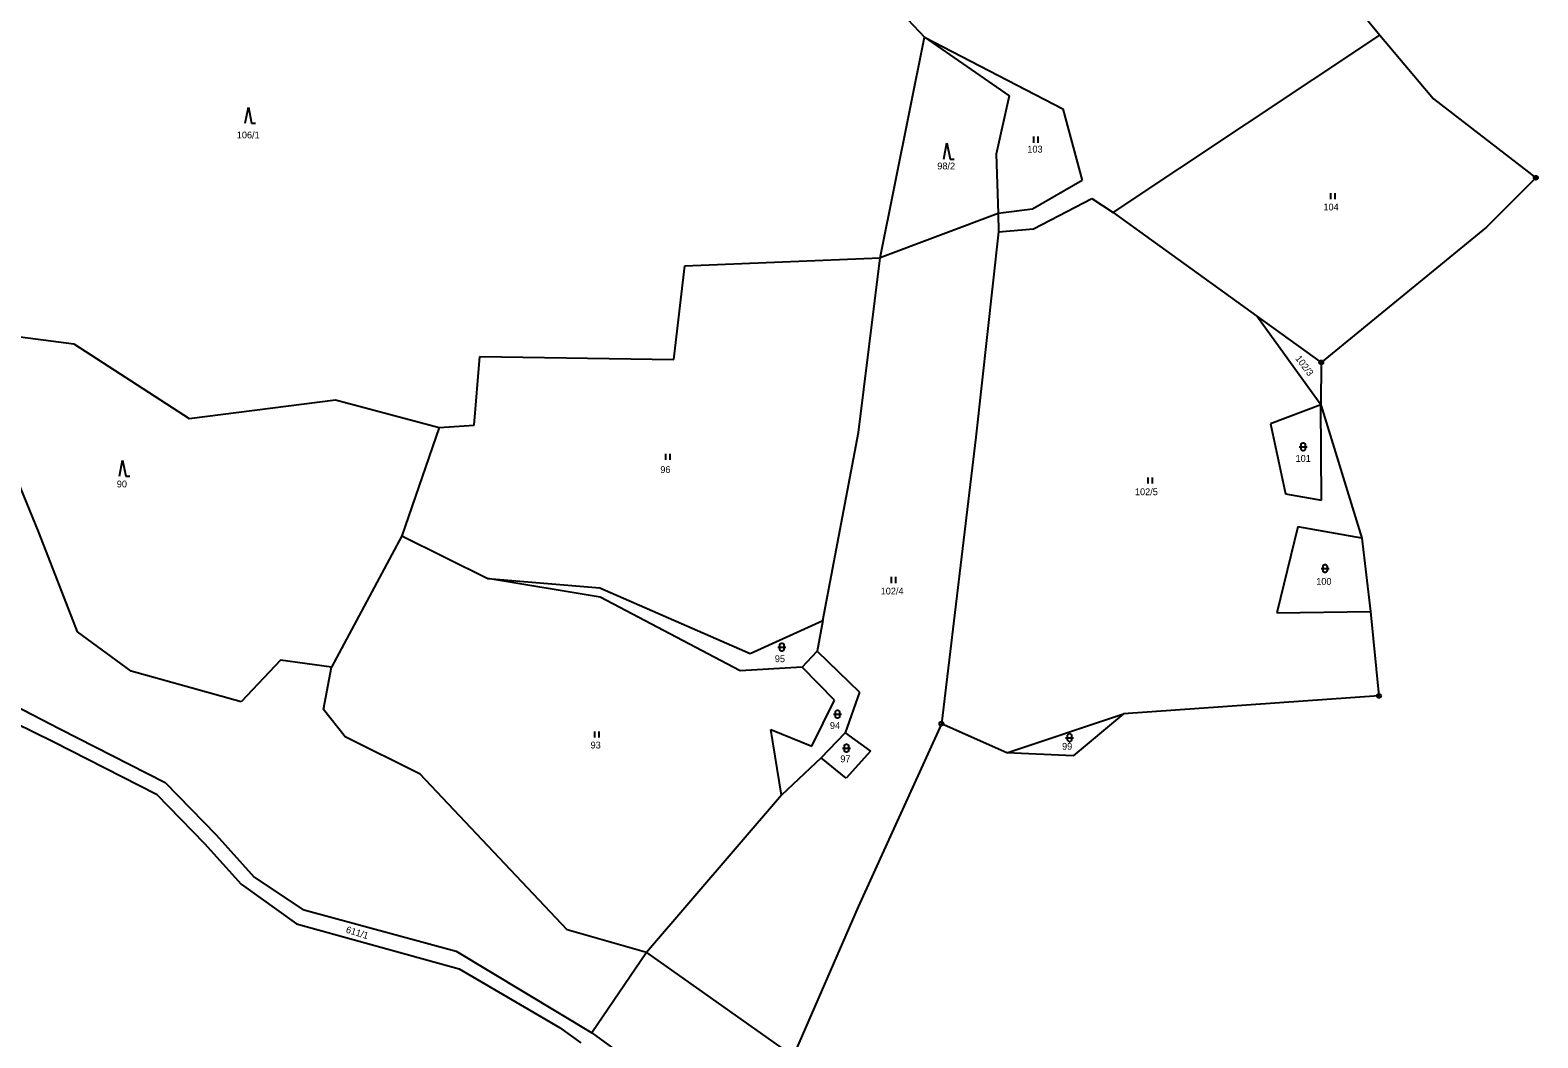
# Model space of a CAD drawing. Extents: x -794421 to -792735, y -1117671 to -1115559.
# Drawn here: x -793109.5 to -792734.9, y -1117082.5 to -1116832.2 of the extents above; entities that cross this region are included whole.
import ezdxf

# ---------------------------------------------------------------- set-up
doc = ezdxf.new("R2010")
doc.units = 0
for name, color, linetype in [('Vrstva 1', 7, 'Continuous'), ('Vrstva 14', 7, 'Continuous'), ('Vrstva 23', 7, 'Continuous'), ('Vrstva 28', 7, 'Continuous'), ('Vrstva 4', 7, 'Continuous')]:
    doc.layers.add(name, color=color, linetype=linetype)

msp = doc.modelspace()

# ---------------------------------------------------------------- linework, layer by layer
at = {"layer": 'Vrstva 1'}
for p, q in [((-792891.38, -1116829.52), (-792887.25, -1116833.92)), ((-792898.31, -1116888.7), (-792887.25, -1116833.92)), ((-792887.25, -1116833.92), (-792866.21, -1116848.49)), ((-792887.25, -1116833.92), (-792852.9, -1116851.76)), ((-792840.44, -1116877.44), (-792774.18, -1116833.45)), ((-792866.21, -1116848.49), (-792869.45, -1116863.01)), ((-792852.9, -1116851.76), (-792848.07, -1116869.51)), ((-792869.45, -1116863.01), (-792868.99, -1116877.73)), ((-792848.07, -1116869.51), (-792860.46, -1116876.65)), ((-792860.46, -1116876.65), (-792868.99, -1116877.73)), ((-792860.19, -1116881.54), (-792845.67, -1116873.97)), ((-792845.67, -1116873.97), (-792840.44, -1116877.44)), ((-792868.99, -1116877.73), (-792898.31, -1116888.7)), ((-792868.99, -1116877.73), (-792868.89, -1116882.24)), ((-792840.44, -1116877.44), (-792804.69, -1116903.19)), ((-792868.89, -1116882.24), (-792874.53, -1116933.29)), ((-792868.89, -1116882.24), (-792860.19, -1116881.54)), ((-792949.57, -1116913.97), (-792946.82, -1116890.73)), ((-792946.82, -1116890.73), (-792898.31, -1116888.7)), ((-792903.65, -1116932.1), (-792898.31, -1116888.7)), ((-792804.69, -1116903.19), (-792788.69, -1116914.72)), ((-792788.82, -1116925.23), (-792804.69, -1116903.19)), ((-793113.92, -1116908.11), (-793098.62, -1116910.09)), ((-793098.62, -1116910.09), (-793070.02, -1116928.65)), ((-792999.18, -1116930.26), (-792997.75, -1116913.2)), ((-792997.75, -1116913.2), (-792949.57, -1116913.97)), ((-793070.02, -1116928.65), (-793033.65, -1116924.01)), ((-793033.65, -1116924.01), (-793007.9, -1116930.84)), ((-792788.82, -1116925.23), (-792801.34, -1116929.96)), ((-792788.62, -1116948.94), (-792788.82, -1116925.23)), ((-793107.29, -1116957.14), (-793118.24, -1116930.56)), ((-793007.9, -1116930.84), (-793017.12, -1116957.77)), ((-793007.9, -1116930.84), (-792999.18, -1116930.26)), ((-792912.55, -1116978.78), (-792903.65, -1116932.1)), ((-792801.34, -1116929.96), (-792797.55, -1116947.34)), ((-792874.53, -1116933.29), (-792883.08, -1117004.44)), ((-792797.55, -1116947.34), (-792788.62, -1116948.94)), ((-792794.55, -1116955.5), (-792799.71, -1116976.92)), ((-792778.63, -1116958.38), (-792794.55, -1116955.5)), ((-793097.72, -1116981.65), (-793107.29, -1116957.14)), ((-793017.12, -1116957.77), (-793034.62, -1116990.42)), ((-793017.12, -1116957.77), (-792995.79, -1116968.4)), ((-792995.79, -1116968.4), (-792967.97, -1116970.67)), ((-792967.83, -1116973.03), (-792995.79, -1116968.4)), ((-792967.97, -1116970.67), (-792930.61, -1116986.96)), ((-792933.08, -1116991.34), (-792967.83, -1116973.03)), ((-792799.71, -1116976.92), (-792776.46, -1116976.6)), ((-793084.36, -1116991.42), (-793097.72, -1116981.65)), ((-792930.61, -1116986.96), (-792912.55, -1116978.78)), ((-792912.55, -1116978.78), (-792913.94, -1116986.38)), ((-793047.32, -1116988.66), (-793057.06, -1116999.04)), ((-793034.62, -1116990.42), (-793047.32, -1116988.66)), ((-792917.7, -1116990.41), (-792913.94, -1116986.38)), ((-792913.94, -1116986.38), (-792903.41, -1116996.61)), ((-793057.06, -1116999.04), (-793084.36, -1116991.42)), ((-793036.59, -1117000.87), (-793034.62, -1116990.42)), ((-792917.7, -1116990.41), (-792933.08, -1116991.34)), ((-792909.63, -1116998.62), (-792917.7, -1116990.41)), ((-793125.63, -1116993.61), (-793102.09, -1117005.68)), ((-792903.41, -1116996.61), (-792906.97, -1117006.74)), ((-793127.56, -1116997.16), (-793103.79, -1117008.89)), ((-792915.27, -1117010.02), (-792909.63, -1116998.62)), ((-793031.25, -1117007.67), (-793036.59, -1117000.87)), ((-792866.79, -1117011.69), (-792837.82, -1117001.97)), ((-793102.09, -1117005.68), (-793075.99, -1117019.08)), ((-793012.6, -1117016.93), (-793031.25, -1117007.67)), ((-792922.85, -1117022.16), (-792925.45, -1117005.85)), ((-792925.45, -1117005.85), (-792915.27, -1117010.02)), ((-792912.98, -1117012.95), (-792906.97, -1117006.74)), ((-792906.97, -1117006.74), (-792900.68, -1117011.27)), ((-793103.79, -1117008.89), (-793078.12, -1117021.96)), ((-792900.68, -1117011.27), (-792906.78, -1117017.94)), ((-792912.98, -1117012.95), (-792922.85, -1117022.16)), ((-792906.78, -1117017.94), (-792912.98, -1117012.95)), ((-793075.99, -1117019.08), (-793063.31, -1117032.01)), ((-792976.06, -1117055.61), (-793012.6, -1117016.93)), ((-793078.12, -1117021.96), (-793066.18, -1117034.15)), ((-792922.85, -1117022.16), (-792956.35, -1117061.26)), ((-793066.18, -1117034.15), (-793057.07, -1117044.3)), ((-793063.31, -1117032.01), (-793053.88, -1117042.51)), ((-793057.07, -1117044.3), (-793043.32, -1117054.11)), ((-793053.88, -1117042.51), (-793041.75, -1117050.55)), ((-793041.75, -1117050.55), (-793003.67, -1117060.94)), ((-793043.32, -1117054.11), (-793002.94, -1117065.35)), ((-792956.35, -1117061.26), (-792976.06, -1117055.61)), ((-793003.67, -1117060.94), (-792969.93, -1117081.25)), ((-792956.35, -1117061.26), (-792969.93, -1117081.25)), ((-792956.35, -1117061.26), (-792919.93, -1117087.01)), ((-793002.94, -1117065.35), (-792977.94, -1117079.87)), ((-792977.94, -1117079.87), (-792972.66, -1117083.66)), ((-792969.93, -1117081.25), (-792952.88, -1117093.55))]:
    msp.add_line(p, q, dxfattribs=at)
at = {"layer": 'Vrstva 23'}
for p, q in [((-793056.08, -1116855.27), (-793055.28, -1116851.27)), ((-793055.28, -1116851.27), (-793054.48, -1116855.27)), ((-793054.48, -1116855.27), (-793053.48, -1116855.27)), ((-792882.49, -1116864.2), (-792881.69, -1116860.2)), ((-792881.69, -1116860.2), (-792880.89, -1116864.2)), ((-792860.11, -1116860.13), (-792860.11, -1116858.63)), ((-792859.11, -1116858.63), (-792859.11, -1116860.13)), ((-792880.89, -1116864.2), (-792879.89, -1116864.2)), ((-792786.3, -1116874.15), (-792786.3, -1116872.65)), ((-792785.3, -1116872.65), (-792785.3, -1116874.15)), ((-792794.19, -1116935.64), (-792792.19, -1116935.64)), ((-792793.69, -1116935.04), (-792793.59, -1116934.84)), ((-792793.69, -1116936.24), (-792793.69, -1116935.04)), ((-792793.59, -1116936.44), (-792793.69, -1116936.24)), ((-792793.59, -1116934.84), (-792793.49, -1116934.74)), ((-792793.49, -1116936.54), (-792793.59, -1116936.44)), ((-792793.49, -1116934.74), (-792793.29, -1116934.64)), ((-792793.29, -1116936.64), (-792793.49, -1116936.54)), ((-792793.29, -1116934.64), (-792793.09, -1116934.64)), ((-792793.09, -1116936.64), (-792793.29, -1116936.64)), ((-792793.09, -1116934.64), (-792792.89, -1116934.74)), ((-792792.89, -1116936.54), (-792793.09, -1116936.64)), ((-792792.89, -1116934.74), (-792792.79, -1116934.84)), ((-792792.79, -1116936.44), (-792792.89, -1116936.54)), ((-792792.79, -1116934.84), (-792792.69, -1116935.04)), ((-792792.69, -1116936.24), (-792792.79, -1116936.44)), ((-792792.69, -1116935.04), (-792792.69, -1116936.24)), ((-793087.32, -1116942.98), (-793086.52, -1116938.98)), ((-793086.52, -1116938.98), (-793085.72, -1116942.98)), ((-792951.56, -1116938.88), (-792951.56, -1116937.38)), ((-792950.56, -1116937.38), (-792950.56, -1116938.88)), ((-793085.72, -1116942.98), (-793084.72, -1116942.98)), ((-792831.71, -1116944.76), (-792831.71, -1116943.26)), ((-792830.71, -1116943.26), (-792830.71, -1116944.76)), ((-792788.76, -1116965.9), (-792786.76, -1116965.9)), ((-792788.26, -1116965.3), (-792788.16, -1116965.1)), ((-792788.26, -1116966.5), (-792788.26, -1116965.3)), ((-792788.16, -1116966.7), (-792788.26, -1116966.5)), ((-792788.16, -1116965.1), (-792788.06, -1116965)), ((-792788.06, -1116966.8), (-792788.16, -1116966.7)), ((-792788.06, -1116965), (-792787.86, -1116964.9)), ((-792787.86, -1116966.9), (-792788.06, -1116966.8)), ((-792787.86, -1116964.9), (-792787.66, -1116964.9)), ((-792787.66, -1116966.9), (-792787.86, -1116966.9)), ((-792787.66, -1116964.9), (-792787.46, -1116965)), ((-792787.46, -1116966.8), (-792787.66, -1116966.9)), ((-792787.46, -1116965), (-792787.36, -1116965.1)), ((-792787.36, -1116966.7), (-792787.46, -1116966.8)), ((-792787.36, -1116965.1), (-792787.26, -1116965.3)), ((-792787.26, -1116966.5), (-792787.36, -1116966.7)), ((-792787.26, -1116965.3), (-792787.26, -1116966.5)), ((-792895.5, -1116969.5), (-792895.5, -1116968)), ((-792894.5, -1116968), (-792894.5, -1116969.5)), ((-792923.73, -1116985.4), (-792921.73, -1116985.4)), ((-792923.23, -1116984.8), (-792923.13, -1116984.6)), ((-792923.23, -1116986), (-792923.23, -1116984.8)), ((-792923.13, -1116984.6), (-792923.03, -1116984.5)), ((-792923.03, -1116984.5), (-792922.83, -1116984.4)), ((-792922.83, -1116984.4), (-792922.63, -1116984.4)), ((-792922.63, -1116984.4), (-792922.43, -1116984.5)), ((-792922.43, -1116984.5), (-792922.33, -1116984.6)), ((-792922.33, -1116984.6), (-792922.23, -1116984.8)), ((-792922.23, -1116984.8), (-792922.23, -1116986)), ((-792923.13, -1116986.2), (-792923.23, -1116986)), ((-792923.03, -1116986.3), (-792923.13, -1116986.2)), ((-792922.83, -1116986.4), (-792923.03, -1116986.3)), ((-792922.63, -1116986.4), (-792922.83, -1116986.4)), ((-792922.43, -1116986.3), (-792922.63, -1116986.4)), ((-792922.33, -1116986.2), (-792922.43, -1116986.3)), ((-792922.23, -1116986), (-792922.33, -1116986.2)), ((-792909.9, -1117002.1), (-792907.9, -1117002.1)), ((-792909.4, -1117001.5), (-792909.3, -1117001.3)), ((-792909.4, -1117002.7), (-792909.4, -1117001.5)), ((-792909.3, -1117002.9), (-792909.4, -1117002.7)), ((-792909.3, -1117001.3), (-792909.2, -1117001.2)), ((-792909.2, -1117003), (-792909.3, -1117002.9)), ((-792909.2, -1117001.2), (-792909, -1117001.1)), ((-792909, -1117003.1), (-792909.2, -1117003)), ((-792909, -1117001.1), (-792908.8, -1117001.1)), ((-792908.8, -1117003.1), (-792909, -1117003.1)), ((-792908.8, -1117001.1), (-792908.6, -1117001.2)), ((-792908.6, -1117003), (-792908.8, -1117003.1)), ((-792908.6, -1117001.2), (-792908.5, -1117001.3)), ((-792908.5, -1117002.9), (-792908.6, -1117003)), ((-792908.5, -1117001.3), (-792908.4, -1117001.5)), ((-792908.4, -1117002.7), (-792908.5, -1117002.9)), ((-792908.4, -1117001.5), (-792908.4, -1117002.7)), ((-792969.23, -1117007.89), (-792969.23, -1117006.39)), ((-792968.23, -1117006.39), (-792968.23, -1117007.89)), ((-792852.22, -1117007.91), (-792850.22, -1117007.91)), ((-792851.72, -1117007.31), (-792851.62, -1117007.11)), ((-792851.72, -1117008.51), (-792851.72, -1117007.31)), ((-792851.62, -1117007.11), (-792851.52, -1117007.01)), ((-792851.52, -1117007.01), (-792851.32, -1117006.91)), ((-792851.32, -1117006.91), (-792851.12, -1117006.91)), ((-792851.12, -1117006.91), (-792850.92, -1117007.01)), ((-792850.92, -1117007.01), (-792850.82, -1117007.11)), ((-792850.82, -1117007.11), (-792850.72, -1117007.31)), ((-792850.72, -1117007.31), (-792850.72, -1117008.51)), ((-792907.68, -1117010.51), (-792905.68, -1117010.51)), ((-792907.18, -1117009.91), (-792907.08, -1117009.71)), ((-792907.18, -1117011.11), (-792907.18, -1117009.91)), ((-792907.08, -1117011.31), (-792907.18, -1117011.11)), ((-792907.08, -1117009.71), (-792906.98, -1117009.61)), ((-792906.98, -1117011.41), (-792907.08, -1117011.31)), ((-792906.98, -1117009.61), (-792906.78, -1117009.51)), ((-792906.78, -1117011.51), (-792906.98, -1117011.41)), ((-792906.78, -1117009.51), (-792906.58, -1117009.51)), ((-792906.58, -1117011.51), (-792906.78, -1117011.51)), ((-792906.58, -1117009.51), (-792906.38, -1117009.61)), ((-792906.38, -1117011.41), (-792906.58, -1117011.51)), ((-792906.38, -1117009.61), (-792906.28, -1117009.71)), ((-792906.28, -1117011.31), (-792906.38, -1117011.41)), ((-792906.28, -1117009.71), (-792906.18, -1117009.91)), ((-792906.18, -1117011.11), (-792906.28, -1117011.31)), ((-792906.18, -1117009.91), (-792906.18, -1117011.11)), ((-792851.62, -1117008.71), (-792851.72, -1117008.51)), ((-792851.52, -1117008.81), (-792851.62, -1117008.71)), ((-792851.32, -1117008.91), (-792851.52, -1117008.81)), ((-792851.12, -1117008.91), (-792851.32, -1117008.91)), ((-792850.92, -1117008.81), (-792851.12, -1117008.91)), ((-792850.82, -1117008.71), (-792850.92, -1117008.81)), ((-792850.72, -1117008.51), (-792850.82, -1117008.71))]:
    msp.add_line(p, q, dxfattribs=at)
at = {"layer": 'Vrstva 28'}
for centre, radius in [((-792735.38, -1116868.83), 0.5), ((-792735.38, -1116868.83), 0.01), ((-792788.69, -1116914.72), 0.5), ((-792788.69, -1116914.72), 0.01), ((-792774.35, -1116997.52), 0.5), ((-792774.35, -1116997.52), 0.01), ((-792883.08, -1117004.44), 0.5), ((-792883.08, -1117004.44), 0.01)]:
    msp.add_circle(centre, radius, dxfattribs=at)
at = {"layer": 'Vrstva 4'}
for p, q in [((-792790.45, -1116813.45), (-792774.18, -1116833.45)), ((-792774.18, -1116833.45), (-792760.77, -1116849.25)), ((-792760.77, -1116849.25), (-792735.38, -1116868.83)), ((-792735.38, -1116868.83), (-792747.65, -1116881.11)), ((-792747.65, -1116881.11), (-792788.69, -1116914.72)), ((-792788.69, -1116914.72), (-792788.82, -1116925.23)), ((-792788.82, -1116925.23), (-792778.63, -1116958.38)), ((-792778.63, -1116958.38), (-792776.46, -1116976.6)), ((-792776.46, -1116976.6), (-792774.35, -1116997.52)), ((-792774.35, -1116997.52), (-792837.82, -1117001.97)), ((-792883.08, -1117004.44), (-792903.79, -1117049.93)), ((-792866.79, -1117011.69), (-792883.08, -1117004.44)), ((-792837.82, -1117001.97), (-792850.3, -1117012.39)), ((-792850.3, -1117012.39), (-792866.79, -1117011.69)), ((-792903.79, -1117049.93), (-792919.93, -1117087.01))]:
    msp.add_line(p, q, dxfattribs=at)

# ---------------------------------------------------------------- texts
at = {"layer": 'Vrstva 14'}
for s, p in [('106/1', (-793058.156, -1116859.07)), ('103', (-792861.729, -1116862.59)), ('98/2', (-792884.1, -1116866.77)), ('104', (-792788.165, -1116876.97)), ('96', (-792952.917, -1116942.16)), ('101', (-792795.082, -1116939.4)), ('90', (-793087.966, -1116945.75)), ('102/5', (-792834.988, -1116947.68)), ('102/4', (-792898.178, -1116972.34)), ('100', (-792789.948, -1116969.94)), ('95', (-792924.473, -1116989.15)), ('94', (-792910.783, -1117005.74)), ('93', (-792970.247, -1117010.59)), ('99', (-792853.097, -1117010.9)), ('97', (-792908.193, -1117014.01))]:
    msp.add_text(s, height=1.7, dxfattribs=at).set_placement(p)
for s, rotation, p in [('102/3', 306.89316, (-792795.252, -1116913.738)), ('611/1', 342.84546, (-793031.186, -1117056.297))]:
    msp.add_text(s, height=1.7, rotation=rotation, dxfattribs=at).set_placement(p)

doc.saveas('drawing.dxf')
